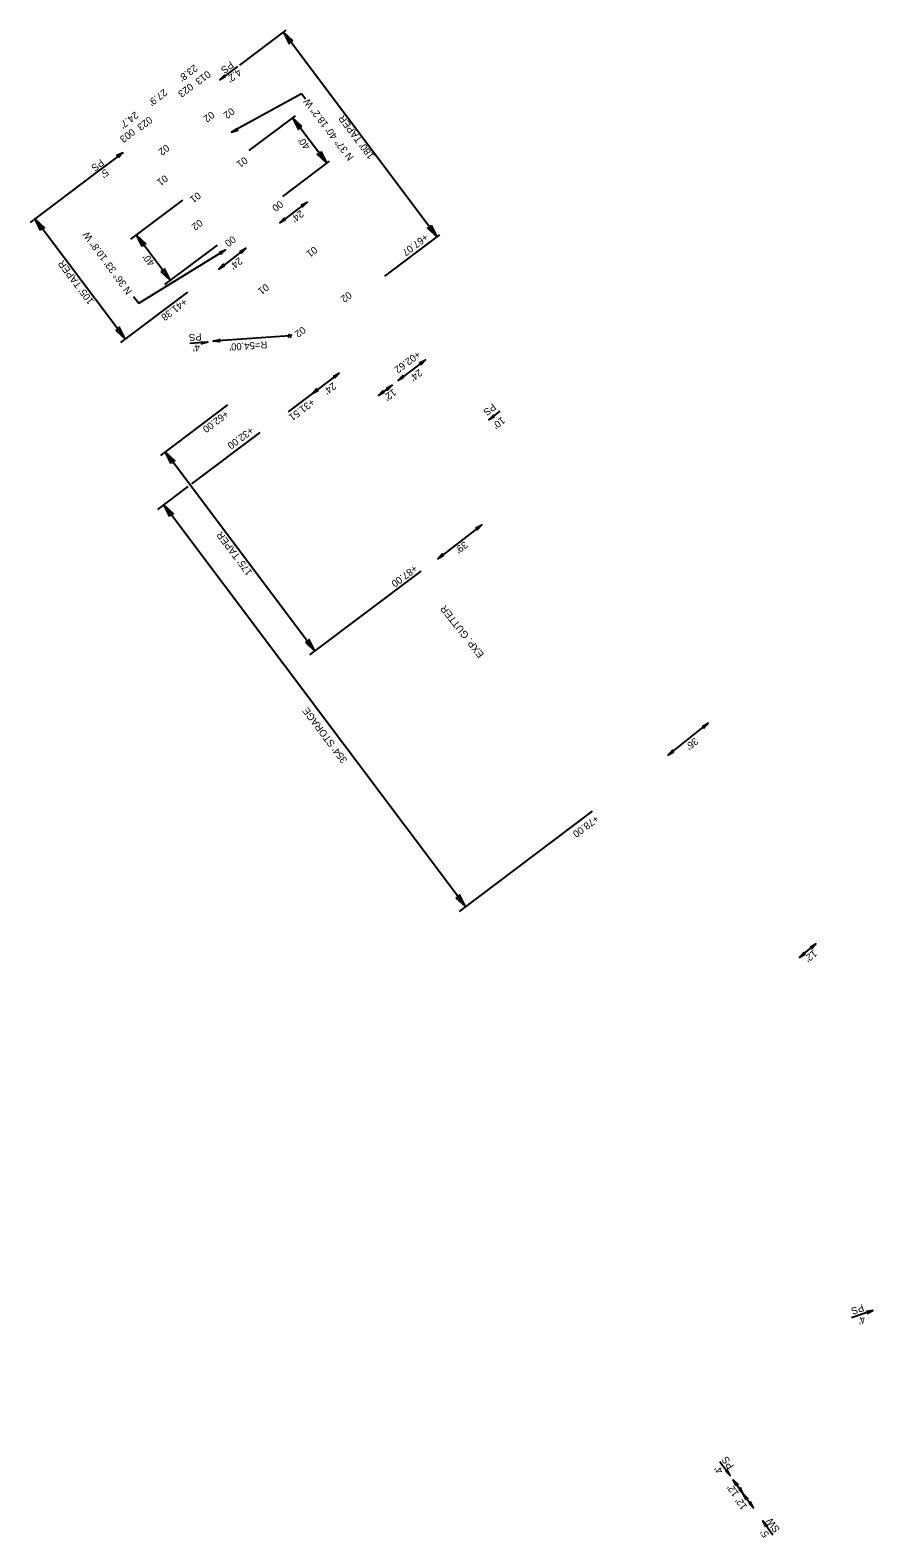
# Model space of a CAD drawing. Extents: x 1262642 to 1268358, y 767825 to 773481.
# Drawn here: x 1262642 to 1263235, y 769090 to 770151 of the extents above; entities that cross this region are included whole.
import ezdxf

# ---------------------------------------------------------------- set-up
doc = ezdxf.new("R2010")
doc.units = 0
for name, color, linetype in [('Prop Dimension', 7, 'Continuous'), ('Prop Dimension Text', 7, 'Continuous'), ('Prop Terminator CELL', 7, 'Continuous')]:
    doc.layers.add(name, color=color, linetype=linetype)

msp = doc.modelspace()

# ---------------------------------------------------------------- linework, layer by layer
at = {"layer": 'Prop Dimension'}
for p, q in [((1262821.8, 770151.2), (1262789.1, 770126.6)), ((1262928.1, 770005.8), (1262820, 770149.8)), ((1262835.6, 770102.7), (1262832.9, 770106.3)), ((1262828.3, 770090.9), (1262795.6, 770066.4)), ((1262850.5, 770057.6), (1262826.5, 770089.6)), ((1262852.3, 770058.9), (1262819.3, 770034.2)), ((1262712.7, 770004.2), (1262749.3, 770031.6)), ((1262740.6, 769975), (1262716.6, 770007)), ((1262736.7, 769972.2), (1262773.6, 769999.8)), ((1262929.9, 770007.2), (1262891.1, 769978)), ((1262718.2, 769958.8), (1262714.6, 769963.6)), ((1262824.6, 769936), (1262770.7, 769932.4)), ((1262824.6, 769936), (1262823.2, 769935)), ((1262824.6, 769936), (1262823.6, 769937.3)), ((1262826, 769937), (1262824.6, 769936)), ((1262825.6, 769934.6), (1262824.6, 769936)), ((1262766.8, 769931.6), (1262754.2, 769930.7))]:
    msp.add_line(p, q, dxfattribs=at)
at = {"layer": 'Prop Dimension Text'}
for p, q in [((1262787.8, 770125.7), (1262775.4, 770116.2)), ((1262832.9, 770106.3), (1262783.6, 770079.3)), ((1262707, 770064.9), (1262688, 770050.8)), ((1262689, 770051.4), (1262641.8, 770015.9)), ((1262836.7, 770030.2), (1262826.8, 770022.7)), ((1262827.1, 770022.9), (1262817.6, 770015.7)), ((1262708.6, 769933.9), (1262645.3, 770018.2)), ((1262793.6, 769997.7), (1262784, 769990.4)), ((1262793.6, 769997.7), (1262784, 769990.4)), ((1262718.4, 769959), (1262779.4, 769996.7)), ((1262784, 769990.4), (1262774.5, 769983.1)), ((1262752.5, 769966.9), (1262705.3, 769931.4)), ((1262920, 769919.3), (1262910.1, 769911.8)), ((1262920, 769919.3), (1262910.4, 769912)), ((1262859.4, 769909.9), (1262823.4, 769882.6)), ((1262910.4, 769912), (1262900.9, 769904.8)), ((1262896.5, 769901.4), (1262887, 769894.1)), ((1262780.8, 769887.5), (1262733.6, 769852)), ((1262964.7, 769876.9), (1262972.6, 769883)), ((1262755.7, 769832), (1262803.7, 769868.1)), ((1262842.2, 769714.3), (1262737.1, 769854.3)), ((1262731.6, 769813.9), (1262753, 769830)), ((1262948.2, 769534.5), (1262735.9, 769817.2)), ((1262959.6, 769803.1), (1262928.7, 769779.3)), ((1262838.7, 769711.7), (1262917.1, 769770.6)), ((1263090.8, 769641.1), (1263118.9, 769663.6)), ((1262943.9, 769531.2), (1263037.6, 769601.6)), ((1263183.3, 769498.8), (1263194.8, 769508.4)), ((1263234.9, 769250.4), (1263219.8, 769245.2)), ((1263127.3, 769144), (1263134.4, 769134.3)), ((1263136.7, 769131.1), (1263143.7, 769121.3)), ((1263143.7, 769121.3), (1263150.8, 769111.6)), ((1263157.5, 769102.3), (1263164.5, 769092.5))]:
    msp.add_line(p, q, dxfattribs=at)
for points in [[(1262826.6, 770143.6), (1262820, 770149.8), (1262824.1, 770141.6), (1262824.7, 770143.5)], [(1262779.4, 770118.3), (1262775.4, 770116.2), (1262778.5, 770119.6), (1262778.5, 770118.6)], [(1262787.2, 770082.1), (1262783.6, 770079.3), (1262788, 770080.8), (1262787.1, 770081.2)], [(1262833.1, 770083.3), (1262826.5, 770089.6), (1262830.6, 770081.4), (1262831.2, 770083.2)], [(1262703.9, 770061.6), (1262707, 770064.9), (1262702.9, 770062.9), (1262703.9, 770062.6)], [(1262846.3, 770065.7), (1262850.5, 770057.6), (1262843.8, 770063.9), (1262845.7, 770063.9)], [(1262832.6, 770028.1), (1262836.7, 770030.2), (1262833.6, 770026.8), (1262833.6, 770027.8)], [(1262649.3, 770010.3), (1262645.1, 770018.4), (1262651.8, 770012.1), (1262649.9, 770012.1)], [(1262821.6, 770017.8), (1262817.6, 770015.7), (1262820.7, 770019), (1262820.7, 770018.1)], [(1262924, 770014), (1262928.1, 770005.8), (1262921.4, 770012.1), (1262923.4, 770012.2)], [(1262720.7, 769998.9), (1262716.6, 770007), (1262723.3, 770000.8), (1262721.3, 770000.7)], [(1262789.5, 769995.5), (1262793.6, 769997.7), (1262790.5, 769994.3), (1262790.4, 769995.3)], [(1262789.5, 769995.5), (1262793.6, 769997.7), (1262790.5, 769994.3), (1262790.4, 769995.3)], [(1262778.5, 769985.2), (1262774.5, 769983.1), (1262777.6, 769986.5), (1262777.6, 769985.5)], [(1262775.1, 769995), (1262779.4, 769996.7), (1262775.9, 769993.6), (1262776, 769994.6)], [(1262733.9, 769981.3), (1262740.6, 769975), (1262736.4, 769983.2), (1262735.8, 769981.4)], [(1262702, 769940.2), (1262708.6, 769933.9), (1262704.4, 769942.1), (1262703.9, 769940.2)], [(1262915.9, 769917.2), (1262920, 769919.3), (1262916.9, 769915.9), (1262916.8, 769916.9)], [(1262915.9, 769917.2), (1262920, 769919.3), (1262916.9, 769915.9), (1262916.8, 769916.9)], [(1262855.4, 769907.8), (1262859.4, 769909.9), (1262856.3, 769906.5), (1262856.3, 769907.5)], [(1262904.9, 769906.9), (1262900.9, 769904.8), (1262904, 769908.1), (1262904, 769907.1)], [(1262844.4, 769897.5), (1262840.3, 769895.4), (1262843.4, 769898.8), (1262843.5, 769897.8)], [(1262891, 769896.2), (1262887, 769894.1), (1262890.1, 769897.5), (1262890.1, 769896.5)], [(1262892.5, 769899.3), (1262896.5, 769901.4), (1262893.4, 769898), (1262893.4, 769899)], [(1262968.7, 769879.1), (1262964.7, 769876.9), (1262967.8, 769880.3), (1262967.8, 769879.3)], [(1262741.1, 769846.4), (1262736.9, 769854.5), (1262743.6, 769848.2), (1262741.7, 769848.2)], [(1262740.1, 769809), (1262735.9, 769817.2), (1262742.6, 769810.9), (1262740.6, 769810.8)], [(1262955.5, 769801), (1262959.6, 769803.1), (1262956.5, 769799.7), (1262956.5, 769800.7)], [(1262932.7, 769781.4), (1262928.7, 769779.3), (1262931.8, 769782.7), (1262931.8, 769781.7)], [(1262835.6, 769720.6), (1262842.2, 769714.3), (1262838.1, 769722.5), (1262837.5, 769720.7)], [(1263114.9, 769661.4), (1263118.9, 769663.6), (1263115.9, 769660.1), (1263115.8, 769661.1)], [(1263094.8, 769643.3), (1263090.8, 769641.1), (1263093.8, 769644.5), (1263093.9, 769643.6)], [(1262941.5, 769540.7), (1262948.2, 769534.5), (1262944, 769542.7), (1262943.4, 769540.8)], [(1263187.2, 769501.1), (1263183.3, 769498.8), (1263186.3, 769502.3), (1263186.3, 769501.4)], [(1263190.9, 769506.1), (1263194.8, 769508.4), (1263191.9, 769504.9), (1263191.8, 769505.9)], [(1263131.1, 769137.5), (1263134.4, 769134.3), (1263132.4, 769138.4), (1263132, 769137.5)], [(1263138.7, 769127), (1263136.7, 769131.1), (1263140, 769127.9), (1263139, 769127.9)], [(1263140.5, 769124.5), (1263143.7, 769121.3), (1263141.7, 769125.5), (1263141.4, 769124.5)], [(1263145.7, 769117.2), (1263143.7, 769121.3), (1263147, 769118.1), (1263146, 769118.1)], [(1263147.5, 769114.8), (1263150.8, 769111.6), (1263148.8, 769115.8), (1263148.4, 769114.8)], [(1263159.5, 769098.2), (1263157.5, 769102.3), (1263160.8, 769099.1), (1263159.8, 769099.1)]]:
    msp.add_lwpolyline(points, close=True, dxfattribs=at)
at = {"layer": 'Prop Terminator CELL'}
for points in [[(1262775.3, 769931.9), (1262770.7, 769932.4), (1262775.2, 769933.5), (1262774.7, 769932.6)], [(1262762.2, 769932), (1262766.8, 769931.6), (1262762.3, 769930.5), (1262762.8, 769931.3)], [(1263230.9, 769248.2), (1263234.9, 769250.4), (1263230.4, 769249.7), (1263231.2, 769249.1)]]:
    msp.add_lwpolyline(points, close=True, dxfattribs=at)

# ---------------------------------------------------------------- texts
at = {"layer": 'Prop Dimension'}
for s, rotation, p in [('PS', 199.0766, (1263227.6, 769254.9)), ("4'", 199.0766, (1263228.6, 769246.7)), ("4'", 125.8167, (1263129.8, 769137.6)), ('PS', 125.8167, (1263137.4, 769141)), ("12'", 125.8167, (1263140.9, 769121.5)), ("12'", 125.8167, (1263146.8, 769112.3)), ('SW', 125.8167, (1263169.8, 769096.3)), ("5'", 125.8167, (1263162.2, 769092.9))]:
    msp.add_text(s, height=5, rotation=rotation, dxfattribs=at).set_placement(p)
at = {"layer": 'Prop Dimension Text'}
for s, height, rotation, p in [("23.8'", 5, 217.1767, (1262757.3, 770127.3)), ('PS', 5, 217.1767, (1262782.7, 770129.6)), ('013', 5, 217.1767, (1262766.5, 770123)), ("4.2'", 5, 217.1767, (1262788.2, 770124.3)), ("27.9'", 5, 217.1767, (1262735.9, 770110.1)), ('023', 5, 217.1767, (1262754.3, 770114.2)), ("24.7'", 5.01, 217.1767, (1262715.7, 770094.2)), ('02', 5, 217.1767, (1262769.2, 770094.4)), ('02', 5, 217.1767, (1262783.3, 770096.9)), ('N 37%%d 40\' 18.2" W', 5, 127.4573, (1262869.8, 770061.8)), ('023', 5, 217.1767, (1262725.5, 770090.8)), ("180' TAPER", 5, 126.9396, (1262884.3, 770062.8)), ('003', 5, 217.1767, (1262713.3, 770082.3)), ("40'", 5, 126.9396, (1262839.1, 770069.5)), ('02', 5, 217.1767, (1262737.5, 770071.1)), ('01', 5, 217.1767, (1262792.5, 770062.4)), ('PS', 5, 217.1767, (1262691.4, 770060.8)), ("5'", 5, 217.1767, (1262694.7, 770053.9)), ('01', 5, 217.1767, (1262736.4, 770049.7)), ('01', 5, 217.1767, (1262759.6, 770037.6)), ('00', 5, 217.1767, (1262817.5, 770031.6)), ("24'", 5, 217.1767, (1262832, 770024.8)), ('N 36%%d 33\' 10.8" W', 5, 126.3385, (1262713.8, 769967.5)), ('02', 5, 217.1767, (1262760.9, 770018.4)), ('00', 5, 217.1767, (1262784.2, 770006.8)), ('01', 5, 217.1767, (1262841.6, 769999.4)), ('+67.07', 5, 217.1767, (1262919.6, 770008.3)), ("105' TAPER", 5, 126.9057, (1262686.9, 769960.6)), ("40'", 5, 126.9057, (1262729.8, 769987.4)), ("24'", 5, 217.1767, (1262788.9, 769991.6)), ('01', 5, 217.1767, (1262807.5, 769973.1)), ('02', 5, 217.1767, (1262865.8, 769967.6)), ('+41.38', 5, 216.9057, (1262750, 769962.7)), ('PS', 5, 183.8479, (1262762.3, 769937.9)), ('02', 5, 217.1767, (1262833.4, 769943)), ("4'", 5, 183.8479, (1262761.1, 769930.3)), ("R=54.00'", 5, 183.8479, (1262808.5, 769932.4)), ('+02.62', 5, 216.9057, (1262914.2, 769925.8)), ("24'", 5, 217.1767, (1262915.5, 769913)), ("24'", 5, 217.1767, (1262854.9, 769903.6)), ("12'", 5, 217.1767, (1262897.2, 769899.1)), ('+62.00', 5, 216.9057, (1262779.2, 769883.9)), ('+31.51', 5, 217.1767, (1262839.8, 769892.3)), ('PS', 5, 217.643, (1262967.3, 769888.9)), ('+32.00', 5, 216.9057, (1262796.7, 769872.3)), ("10'", 5, 217.643, (1262973.7, 769879.4)), ("175' TAPER", 5, 126.9057, (1262798.5, 769769.7)), ("39'", 5, 217.1767, (1262947.4, 769791.9)), ('+87.00', 5, 216.9057, (1262912, 769775.2)), ('EXP. GUTTER', 5, 128.1225, (1262961.5, 769712)), ("354' STORAGE", 5, 126.9057, (1262865.3, 769637.7)), ("36'", 5, 218.6969, (1263109.5, 769653.7)), ('+78.00', 5, 216.9057, (1263039.7, 769599.1)), ("12'", 5, 219.5455, (1263193.1, 769504.4))]:
    msp.add_text(s, height=height, rotation=rotation, dxfattribs=at).set_placement(p)

doc.saveas('drawing.dxf')
